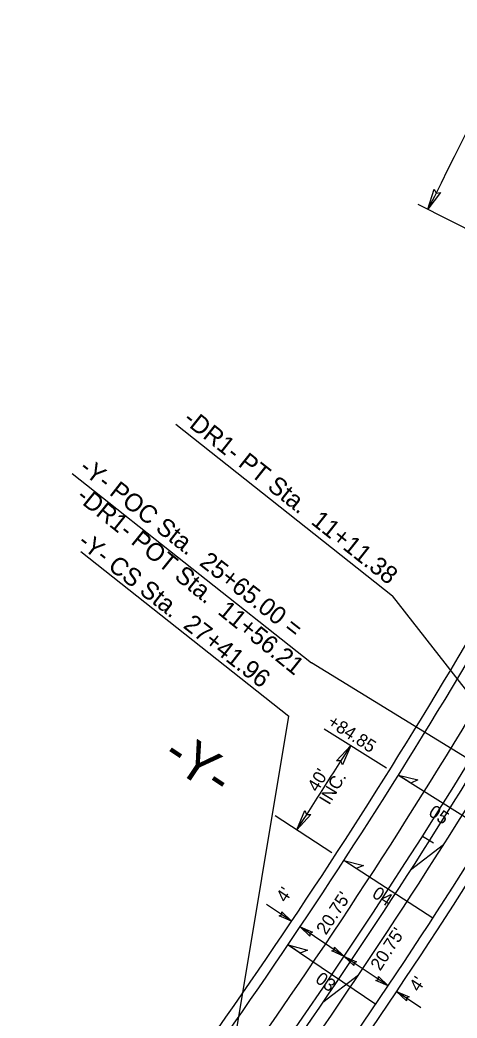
# Model space of a CAD drawing. Extents: x 1778969 to 1790720, y 807089 to 817794.
# Drawn here: x 1782528 to 1782699.2, y 814443.8 to 814834.8 of the extents above; entities that cross this region are included whole.
import ezdxf

# ---------------------------------------------------------------- set-up
doc = ezdxf.new("R2010")
doc.units = 0
for name, color, linetype in [('Prop Dimension', 7, 'Continuous'), ('Prop Dimension Text', 7, 'Continuous'), ('Prop EOT', 7, 'Continuous'), ('Prop Hatching', 7, 'Continuous'), ('Prop Horizontal Alignment', 7, 'Continuous'), ('Prop Horizontal Alignment Station Label', 7, 'Continuous'), ('Prop Horizontal Alignment Tick Small', 7, 'Continuous'), ('Prop Lane Lines', 7, 'Continuous'), ('Prop Paved Shoulder', 7, 'Continuous'), ('Prop Superelevation  Arrow CELL', 7, 'Continuous'), ('Prop Superelevation Label', 7, 'Continuous'), ('Prop Terminator CELL', 7, 'Continuous')]:
    doc.layers.add(name, color=color, linetype=linetype)

msp = doc.modelspace()

# ---------------------------------------------------------------- linework, layer by layer
at = {"layer": 'Prop Dimension'}
for p, q in [((1782683.8, 814762.66), (1782770.22, 814718.61)), ((1782647.07, 814557.18), (1782671.59, 814541.83)), ((1782650.19, 814508.58), (1782627.94, 814523.04)), ((1782634.38, 814481.75), (1782624.58, 814488.31)), ((1782654.94, 814467.98), (1782637.7, 814479.53)), ((1782672.19, 814456.44), (1782654.94, 814467.98)), ((1782685.02, 814447.85), (1782675.51, 814454.21))]:
    msp.add_line(p, q, dxfattribs=at)
for radius, start, end in [(2210, 332.9908, 342.60824), (2287.24, 326.96983, 327.95345)]:
    msp.add_arc((1780718.82, 815764.26), radius, start, end, dxfattribs=at)
at = {"layer": 'Prop EOT'}
for radius, start in [(2309.25, 324.08998), (2350.75, 323.92554)]:
    msp.add_arc((1780718.82, 815764.26), radius, start, 332.9908, dxfattribs=at)
at = {"layer": 'Prop Hatching'}
for p, q in [((1782693.87, 814511.69), (1782680.97, 814501.71)), ((1782660.57, 814460.66), (1782646.64, 814449.89))]:
    msp.add_line(p, q, dxfattribs=at)
at = {"layer": 'Prop Horizontal Alignment'}
for centre, radius, start, end in [((1784215.14, 816723.19), 2900, 214.79915, 237.40395), ((1780718.82, 815764.26), 2330, 324.08998, 342.60824)]:
    msp.add_arc(centre, radius, start, end, dxfattribs=at)
at = {"layer": 'Prop Horizontal Alignment Station Label'}
for p, q in [((1782589.1, 814676.4), (1782673.91, 814609.25)), ((1782548.42, 814657.19), (1782642.19, 814582.95)), ((1782551.78, 814626.62), (1782633.29, 814562.08)), ((1782741.52, 814522.53), (1782673.91, 814609.25)), ((1782702.96, 814545.6), (1782642.19, 814582.95)), ((1782606.22, 814399.17), (1782633.29, 814562.08))]:
    msp.add_line(p, q, dxfattribs=at)
at = {"layer": 'Prop Horizontal Alignment Tick Small'}
msp.add_line((1782685.69, 814515.13), (1782689.91, 814512.45), dxfattribs=at)
at = {"layer": 'Prop Lane Lines'}
for radius, end in [(2321.25, 333.45226), (2333.25, 332.9908), (2338.75, 332.9908)]:
    msp.add_arc((1780718.82, 815764.26), radius, 324.13824, end, dxfattribs=at)
at = {"layer": 'Prop Paved Shoulder'}
for radius, start in [(2305.25, 324.08998), (2354.75, 323.92554)]:
    msp.add_arc((1780718.82, 815764.26), radius, start, 332.9908, dxfattribs=at)
at = {"layer": 'Prop Superelevation  Arrow CELL'}
for p, q in [((1782676.18, 814538.96), (1782711.36, 814516.94)), ((1782689.65, 814482.92), (1782654.86, 814505.54)), ((1782632.97, 814472.49), (1782667.37, 814449.27))]:
    msp.add_line(p, q, dxfattribs=at)
for points in [[(1782676.18, 814538.96), (1782683.87, 814537.1), (1782681.08, 814535.89)], [(1782654.86, 814505.54), (1782662.51, 814503.54), (1782659.71, 814502.38)], [(1782632.97, 814472.49), (1782640.58, 814470.36), (1782637.76, 814469.25)]]:
    msp.add_lwpolyline(points, close=True, dxfattribs=at)
at = {"layer": 'Prop Terminator CELL'}
for points in [[(1782692.71, 814767.21), (1782687.79, 814760.63), (1782690.2, 814768.54), (1782691.01, 814766.96)], [(1782652, 814544.55), (1782657.53, 814550.63), (1782654.37, 814542.99), (1782653.71, 814544.64)], [(1782641.95, 814523.61), (1782636.41, 814517.53), (1782639.58, 814525.17), (1782640.24, 814523.52)], [(1782630.57, 814485.38), (1782634.38, 814481.75), (1782629.53, 814483.89), (1782630.6, 814484.29)], [(1782641.57, 814475.96), (1782637.7, 814479.53), (1782642.58, 814477.47), (1782641.52, 814477.06)], [(1782651.13, 814471.61), (1782654.94, 814467.98), (1782650.1, 814470.12), (1782651.16, 814470.52)], [(1782658.79, 814464.39), (1782654.94, 814467.98), (1782659.81, 814465.9), (1782658.75, 814465.49)], [(1782668.38, 814460.07), (1782672.19, 814456.44), (1782667.34, 814458.57), (1782668.41, 814458.97)], [(1782679.35, 814450.62), (1782675.51, 814454.21), (1782680.37, 814452.13), (1782679.32, 814451.72)]]:
    msp.add_lwpolyline(points, close=True, dxfattribs=at)

# ---------------------------------------------------------------- texts
at = {"layer": 'Prop Dimension Text'}
for s, rotation, p in [('+84.85', 327.0736, (1782648.02, 814558.71)), ("40'", 58.9737, (1782644.49, 814532.06)), ('INC.', 58.9737, (1782649.1, 814527.01)), ("4'", 56.8252, (1782632.11, 814488.79)), ("20.75'", 56.8252, (1782647.84, 814476.1)), ("20.75'", 56.8252, (1782669.05, 814462.02)), ("4'", 56.8252, (1782684.24, 814453.8))]:
    msp.add_text(s, height=5, rotation=rotation, dxfattribs=at).set_placement(p)
at = {"layer": 'Prop Horizontal Alignment Station Label'}
for s, height, rotation, p in [('-DR1- PT Sta.  11+11.38', 7, 321.5651, (1782591.48, 814677.47)), ('-Y- POC Sta.  25+65.00 =', 7, 321.969, (1782550.76, 814658.38)), ('-DR1- POT Sta.  11+56.21', 7, 321.0497, (1782549.64, 814647.24)), ('-Y- CS Sta.  27+41.96', 7, 321.969, (1782550.17, 814629.36)), ('-Y-', 15, 326.0102, (1782582.99, 814544.81))]:
    msp.add_text(s, height=height, rotation=rotation, dxfattribs=at).set_placement(p)
at = {"layer": 'Prop Superelevation Label'}
for s, rotation, p in [('05', 327.0252, (1782687.62, 814523.45)), ('04', 327.0252, (1782665.52, 814491.48)), ('03', 323.9007, (1782643.29, 814458.21))]:
    msp.add_text(s, height=5, rotation=rotation, dxfattribs=at).set_placement(p)

doc.saveas('drawing.dxf')
